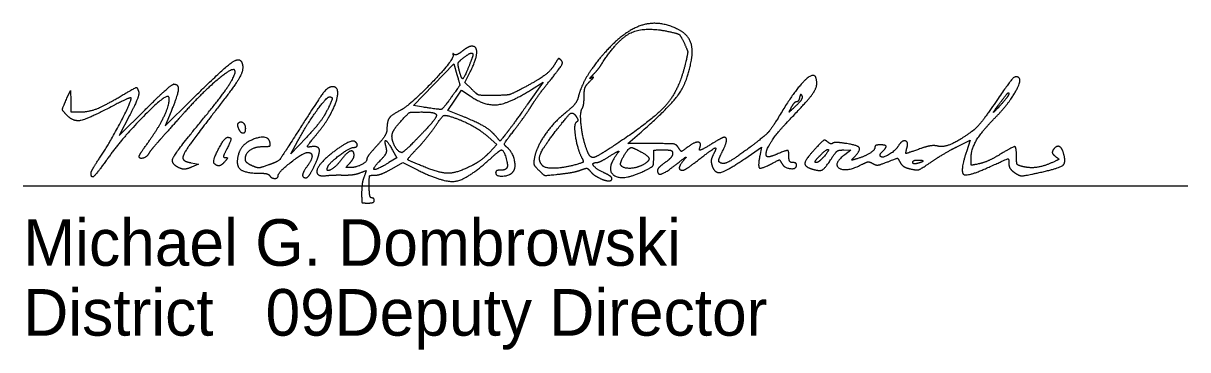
# Model space of a CAD drawing. Extents: x 0 to 45.4, y -2.2 to 22.
# Drawn here: x 26.722 to 30.222, y 3.58 to 4.561 of the extents above; entities that cross this region are included whole.
import ezdxf

# ---------------------------------------------------------------- set-up
doc = ezdxf.new("R2010")
doc.units = 0
doc.layers.add('SH_Data', color=7, linetype='Continuous')
doc.layers.add('SH_Text', color=7, linetype='Continuous')

msp = doc.modelspace()

# ---------------------------------------------------------------- linework, layer by layer
at = {"layer": 'SH_Data'}
msp.add_line((26.722, 4.0723), (30.222, 4.0723), dxfattribs=at)
at = {"layer": 'SH_Text'}
for p, q in [((29.063, 4.3434), (29.063, 4.3434)), ((27.3692, 4.2454), (27.3692, 4.2454)), ((27.296, 4.1396), (27.296, 4.1396)), ((26.9258, 4.1113), (26.9258, 4.1113))]:
    msp.add_line(p, q, dxfattribs=at)
for points in [[(27.9252, 4.3088), (27.8948, 4.3136), (28.0157, 4.4393), (28.0252, 4.4072)], [(28.0691, 4.3637), (28.0492, 4.3835), (28.0651, 4.4147)], [(28.2496, 4.3621), (28.2847, 4.3843), (28.238, 4.3183)], [(26.8533, 4.3362), (26.8638, 4.359), (26.8644, 4.3267)], [(28.0386, 4.283), (27.9983, 4.2993), (28.0187, 4.3297), (28.0392, 4.3601), (28.065, 4.3425)], [(27.1662, 4.2962), (27.1483, 4.2526), (27.2252, 4.3286)], [(27.0417, 4.2842), (27.0104, 4.2235), (27.0879, 4.3008)], [(27.5718, 4.2166), (27.5264, 4.169), (27.5472, 4.2077)], [(28.119, 4.22), (28.1456, 4.197), (28.1228, 4.1728)], [(28.6114, 4.1994), (28.5392, 4.1994), (28.574, 4.2298)], [(29.5295, 4.1906), (29.5682, 4.2099), (29.5568, 4.1751)], [(27.8319, 4.1801), (27.845, 4.1571), (27.8205, 4.1422)], [(28.8903, 4.154), (28.9406, 4.1884), (28.9357, 4.1625)], [(29.1888, 4.1803), (29.2096, 4.1801), (29.1913, 4.166)], [(27.2266, 4.1417), (27.2488, 4.1373), (27.228, 4.1287)], [(27.8293, 4.1236), (27.8625, 4.1426), (27.9084, 4.1197)]]:
    msp.add_lwpolyline(points, dxfattribs=at)
for points in [[(28.689, 4.5431), (28.6322, 4.5715), (28.5268, 4.5374), (28.4692, 4.4719)], [(28.461, 4.4394), (28.5081, 4.5131), (28.5886, 4.5518), (28.662, 4.5362)], [(28.662, 4.5362), (28.6896, 4.5303), (28.6975, 4.5245), (28.708, 4.5024)], [(28.7307, 4.454), (28.7361, 4.4868), (28.7161, 4.5296), (28.689, 4.5431)], [(28.0706, 4.492), (28.0649, 4.492), (28.0517, 4.4853), (28.0412, 4.4771)], [(28.0651, 4.4147), (28.0834, 4.4505), (28.0863, 4.492), (28.0706, 4.492)], [(28.708, 4.5024), (28.7188, 4.4797), (28.7193, 4.4702), (28.7117, 4.4383)], [(27.2252, 4.3286), (27.3196, 4.4219), (27.3721, 4.4608), (27.379, 4.4427)], [(28.0139, 4.4648), (28.0175, 4.453), (27.8844, 4.3142), (27.8551, 4.2992)], [(28.0168, 4.4676), (28.0138, 4.4706), (28.0125, 4.4693), (28.0139, 4.4648)], [(28.0412, 4.4771), (28.0308, 4.4689), (28.0198, 4.4646), (28.0168, 4.4676)], [(28.0318, 4.4216), (28.0278, 4.4377), (28.0304, 4.4453), (28.0433, 4.4558)], [(28.0433, 4.4558), (28.0592, 4.4687), (28.0734, 4.4733), (28.0734, 4.4656)], [(28.0734, 4.4656), (28.0734, 4.4636), (28.0679, 4.4482), (28.0612, 4.4314)], [(28.3081, 4.3928), (28.336, 4.4276), (28.3449, 4.4439), (28.339, 4.4497)], [(28.339, 4.4497), (28.3332, 4.4555), (28.3287, 4.4539), (28.3233, 4.4444)], [(28.4692, 4.4719), (28.4355, 4.4337), (28.3976, 4.3699), (28.39, 4.3388)], [(28.574, 4.2298), (28.6662, 4.3105), (28.7196, 4.3869), (28.7307, 4.454)], [(27.357, 4.4206), (27.3493, 4.4283), (27.2583, 4.3513), (27.2058, 4.2925)], [(27.2639, 4.2754), (27.3181, 4.3408), (27.3644, 4.4131), (27.357, 4.4206)], [(27.379, 4.4427), (27.3859, 4.4247), (27.3639, 4.3814), (27.3171, 4.321)], [(28.0612, 4.4314), (28.0468, 4.3956), (28.039, 4.393), (28.0318, 4.4216)], [(28.3233, 4.4444), (28.3102, 4.4212), (28.2769, 4.3945), (28.2295, 4.369)], [(28.4344, 4.4063), (28.4428, 4.4147), (28.4547, 4.4296), (28.461, 4.4394)], [(28.7117, 4.4383), (28.6928, 4.3596), (28.6163, 4.2716), (28.4999, 4.1947)], [(27.0879, 4.3008), (27.1306, 4.3433), (27.1697, 4.378), (27.1748, 4.378)], [(27.1748, 4.378), (27.1895, 4.378), (27.1859, 4.3438), (27.1662, 4.2962)], [(28.0252, 4.4072), (28.0343, 4.3762), (28.0338, 4.3738), (28.0099, 4.3404)], [(28.2498, 4.3135), (28.2603, 4.3303), (28.2865, 4.366), (28.3081, 4.3928)], [(28.4077, 4.3416), (28.4078, 4.3608), (28.4133, 4.3752), (28.4249, 4.3864)], [(28.4249, 4.3864), (28.4343, 4.3956), (28.4369, 4.4003), (28.4306, 4.397)], [(28.4306, 4.397), (28.4243, 4.3937), (28.426, 4.3979), (28.4344, 4.4063)], [(29.107, 4.3794), (29.107, 4.4207), (29.0453, 4.3676), (28.9943, 4.2825)], [(29.0148, 4.2602), (29.0742, 4.3222), (29.107, 4.3647), (29.107, 4.3794)], [(29.7133, 4.3981), (29.7036, 4.4041), (29.6836, 4.3813), (29.6311, 4.3046)], [(29.6423, 4.2763), (29.6811, 4.3155), (29.725, 4.3908), (29.7133, 4.3981)], [(26.8906, 4.2944), (26.9185, 4.2944), (26.9676, 4.314), (27.0259, 4.3484)], [(27.16, 4.338), (27.1567, 4.3547), (27.0231, 4.2213), (26.9736, 4.152)], [(27.0259, 4.3484), (27.0589, 4.3678), (27.0637, 4.3689), (27.068, 4.3576)], [(27.068, 4.3576), (27.071, 4.3499), (27.0606, 4.3209), (27.0417, 4.2842)], [(27.652, 4.3704), (27.638, 4.3704), (27.6121, 4.3368), (27.5444, 4.2308)], [(27.647, 4.2905), (27.6658, 4.3261), (27.6685, 4.3704), (27.652, 4.3704)], [(28.0099, 4.3404), (27.9839, 4.3042), (27.9749, 4.3008), (27.9252, 4.3088)], [(28.065, 4.3425), (28.1092, 4.3123), (28.1835, 4.3202), (28.2496, 4.3621)], [(28.1363, 4.3441), (28.0952, 4.3439), (28.0864, 4.3464), (28.0691, 4.3637)], [(28.2295, 4.369), (28.1921, 4.3489), (28.1748, 4.3443), (28.1363, 4.3441)], [(28.4013, 4.3036), (28.4048, 4.309), (28.4076, 4.3261), (28.4077, 4.3416)], [(29.0445, 4.3131), (29.0575, 4.3253), (29.0658, 4.3389), (29.063, 4.3434)], [(29.063, 4.3434), (29.06, 4.3481), (29.0569, 4.346), (29.0553, 4.3381)], [(29.6846, 4.3503), (29.6846, 4.3464), (29.674, 4.3314), (29.661, 4.3169)], [(29.668, 4.3353), (29.6771, 4.3474), (29.6846, 4.3541), (29.6846, 4.3503)], [(26.8549, 4.2828), (26.8398, 4.2979), (26.8395, 4.3061), (26.8533, 4.3362)], [(26.9858, 4.3097), (26.9165, 4.2734), (26.8732, 4.2645), (26.8549, 4.2828)], [(26.8644, 4.3267), (26.865, 4.2952), (26.8656, 4.2944), (26.8906, 4.2944)], [(26.9532, 4.1588), (26.983, 4.2029), (27.0501, 4.3323), (27.0455, 4.3368)], [(27.0455, 4.3368), (27.044, 4.3383), (27.0171, 4.3262), (26.9858, 4.3097)], [(27.0967, 4.2021), (27.1296, 4.2478), (27.1634, 4.3204), (27.16, 4.338)], [(27.3171, 4.321), (27.2394, 4.2207), (27.1991, 4.1624), (27.2018, 4.1543)], [(27.5472, 4.2077), (27.5716, 4.2531), (27.6339, 4.3398), (27.6421, 4.3399)], [(27.6421, 4.3399), (27.6516, 4.3401), (27.6486, 4.3258), (27.6325, 4.2942)], [(28.238, 4.3183), (28.2122, 4.282), (28.1839, 4.2429), (28.1749, 4.2315)], [(28.1978, 4.2401), (28.2159, 4.2637), (28.2393, 4.2967), (28.2498, 4.3135)], [(28.39, 4.3388), (28.3873, 4.3276), (28.3712, 4.3076), (28.3543, 4.2942)], [(29.03, 4.3078), (29.0225, 4.2937), (29.0249, 4.2946), (29.0445, 4.3131)], [(29.0459, 4.3248), (29.0422, 4.3248), (29.035, 4.3172), (29.03, 4.3078)], [(29.0553, 4.3381), (29.0539, 4.3308), (29.0496, 4.3248), (29.0459, 4.3248)], [(29.661, 4.3169), (29.6364, 4.2896), (29.6394, 4.2975), (29.668, 4.3353)], [(27.2058, 4.2925), (27.1751, 4.2582), (27.1397, 4.2186), (27.1272, 4.2046)], [(27.1962, 4.1242), (27.1636, 4.1368), (27.1806, 4.1749), (27.2639, 4.2754)], [(27.6325, 4.2942), (27.6241, 4.2777), (27.5967, 4.2428), (27.5718, 4.2166)], [(27.6005, 4.2236), (27.6173, 4.2437), (27.6382, 4.2739), (27.647, 4.2905)], [(27.8551, 4.2992), (27.8284, 4.2855), (27.815, 4.2662), (27.815, 4.2416)], [(27.8564, 4.2659), (27.88, 4.2916), (27.8864, 4.2944), (27.9206, 4.2944)], [(27.9633, 4.2867), (27.9659, 4.2824), (27.9451, 4.255), (27.9169, 4.2259)], [(27.9206, 4.2944), (27.9414, 4.2944), (27.9607, 4.2909), (27.9633, 4.2867)], [(27.9596, 4.2508), (27.9798, 4.2797), (27.9881, 4.2861), (28.0006, 4.2824)], [(28.0006, 4.2824), (28.0364, 4.2719), (28.0941, 4.2415), (28.119, 4.22)], [(28.1419, 4.2221), (28.1282, 4.2386), (28.0847, 4.2642), (28.0386, 4.283)], [(28.3543, 4.2942), (28.3181, 4.2655), (28.265, 4.1902), (28.2587, 4.1586)], [(28.3147, 4.2269), (28.3574, 4.2828), (28.3746, 4.2958), (28.3848, 4.2794)], [(28.3848, 4.2794), (28.3892, 4.2724), (28.3889, 4.2664), (28.3838, 4.2633)], [(28.4167, 4.1785), (28.4044, 4.21), (28.3943, 4.2925), (28.4013, 4.3036)], [(28.9943, 4.2825), (28.9718, 4.2449), (28.9501, 4.2214), (28.9097, 4.191)], [(29.5706, 4.1545), (29.5706, 4.1814), (29.6031, 4.2367), (29.6423, 4.2763)], [(29.6311, 4.3046), (29.6106, 4.2747), (29.5843, 4.2435), (29.5727, 4.2353)], [(27.3692, 4.2454), (27.3667, 4.2518), (27.3666, 4.259), (27.3689, 4.2613)], [(27.3689, 4.2613), (27.3756, 4.268), (27.3894, 4.2567), (27.3894, 4.2446)], [(27.3894, 4.2446), (27.3894, 4.23), (27.3749, 4.2306), (27.3692, 4.2454)], [(27.815, 4.2416), (27.815, 4.2328), (27.8013, 4.2108), (27.7846, 4.1927)], [(27.8302, 4.222), (27.8303, 4.2305), (27.842, 4.2502), (27.8564, 4.2659)], [(27.9073, 4.1861), (27.9221, 4.2018), (27.9456, 4.2309), (27.9596, 4.2508)], [(28.176, 4.188), (28.1666, 4.1959), (28.1698, 4.2035), (28.1978, 4.2401)], [(28.3838, 4.2633), (28.3755, 4.2581), (28.3878, 4.1813), (28.4011, 4.1561)], [(28.9575, 4.1602), (28.9491, 4.1686), (28.9817, 4.2256), (29.0148, 4.2602)], [(29.5727, 4.2353), (29.5319, 4.2065), (29.4872, 4.1877), (29.4699, 4.192)], [(27.0702, 4.1614), (27.0702, 4.1635), (27.0821, 4.1818), (27.0967, 4.2021)], [(27.1272, 4.2046), (27.1147, 4.1906), (27.1017, 4.1742), (27.0983, 4.1683)], [(27.296, 4.1396), (27.2897, 4.1459), (27.3268, 4.2184), (27.3363, 4.2184)], [(27.3363, 4.2184), (27.3469, 4.2184), (27.3456, 4.2059), (27.3322, 4.18)], [(27.4635, 4.2026), (27.4584, 4.2275), (27.3793, 4.201), (27.3699, 4.1712)], [(27.443, 4.1906), (27.46, 4.1906), (27.4654, 4.1937), (27.4635, 4.2026)], [(27.5444, 4.2308), (27.4968, 4.1562), (27.4868, 4.1449), (27.4595, 4.1353)], [(27.5832, 4.1894), (27.574, 4.1877), (27.5793, 4.1981), (27.6005, 4.2236)], [(27.7173, 4.2063), (27.7099, 4.2109), (27.6528, 4.1757), (27.6265, 4.1503)], [(27.715, 4.188), (27.7252, 4.188), (27.7268, 4.2005), (27.7173, 4.2063)], [(27.8129, 4.1876), (27.8069, 4.2105), (27.8168, 4.2066), (27.8319, 4.1801)], [(27.8598, 4.1728), (27.8499, 4.1728), (27.8302, 4.2056), (27.8302, 4.222)], [(27.9169, 4.2259), (27.8887, 4.1967), (27.863, 4.1728), (27.8598, 4.1728)], [(28.1749, 4.2315), (28.156, 4.2075), (28.1544, 4.207), (28.1419, 4.2221)], [(28.2837, 4.1323), (28.2692, 4.1468), (28.281, 4.1827), (28.3147, 4.2269)], [(28.7545, 4.1837), (28.7615, 4.202), (28.7414, 4.2055), (28.72, 4.1897)], [(28.8285, 4.2184), (28.8259, 4.2184), (28.8072, 4.2083), (28.7871, 4.1959)], [(28.8214, 4.1717), (28.8337, 4.1955), (28.8372, 4.2184), (28.8285, 4.2184)], [(29.1397, 4.2045), (29.1314, 4.2113), (29.1237, 4.2071), (29.1029, 4.1844)], [(29.1548, 4.2004), (29.1523, 4.1978), (29.1455, 4.1997), (29.1397, 4.2045)], [(29.194, 4.1999), (29.175, 4.2027), (29.1574, 4.203), (29.1548, 4.2004)], [(29.3784, 4.188), (29.383, 4.2057), (29.3624, 4.2096), (29.3525, 4.193)], [(27.0983, 4.1683), (27.0927, 4.1584), (27.0702, 4.1529), (27.0702, 4.1614)], [(27.3322, 4.18), (27.3243, 4.1648), (27.3234, 4.1576), (27.3293, 4.1576)], [(27.3699, 4.1712), (27.359, 4.137), (27.3863, 4.1105), (27.4321, 4.1105)], [(27.3894, 4.1525), (27.3894, 4.1698), (27.4186, 4.1906), (27.443, 4.1906)], [(27.4882, 4.1038), (27.4882, 4.1136), (27.564, 4.1728), (27.5766, 4.1728)], [(27.5766, 4.1728), (27.5902, 4.1728), (27.5895, 4.1502), (27.5754, 4.1315)], [(27.5964, 4.1313), (27.6146, 4.1689), (27.6089, 4.1941), (27.5832, 4.1894)], [(27.6373, 4.13), (27.6421, 4.1417), (27.7041, 4.188), (27.715, 4.188)], [(27.7162, 4.1639), (27.7162, 4.1805), (27.6939, 4.1729), (27.6775, 4.1507)], [(27.7846, 4.1927), (27.7679, 4.1746), (27.7542, 4.1564), (27.7542, 4.1523)], [(27.7956, 4.1496), (27.8101, 4.1647), (27.8157, 4.177), (27.8129, 4.1876)], [(27.9334, 4.1269), (27.8782, 4.1491), (27.8763, 4.1534), (27.9073, 4.1861)], [(28.1228, 4.1728), (28.1103, 4.1595), (28.0869, 4.1419), (28.071, 4.1337)], [(28.1248, 4.1531), (28.1414, 4.1681), (28.1569, 4.1804), (28.1591, 4.1804)], [(28.1591, 4.1804), (28.1657, 4.1804), (28.1799, 4.1336), (28.1755, 4.1264)], [(28.1938, 4.1144), (28.204, 4.1267), (28.1925, 4.1743), (28.176, 4.188)], [(28.4343, 4.1576), (28.4291, 4.1576), (28.4212, 4.167), (28.4167, 4.1785)], [(28.4999, 4.1947), (28.4691, 4.1743), (28.4396, 4.1576), (28.4343, 4.1576)], [(28.4858, 4.1627), (28.5035, 4.1738), (28.5142, 4.1781), (28.5097, 4.1722)], [(28.5097, 4.1722), (28.4709, 4.1221), (28.5247, 4.086), (28.5902, 4.1182)], [(28.5181, 4.1347), (28.5142, 4.141), (28.5424, 4.188), (28.5502, 4.188)], [(28.5502, 4.188), (28.5517, 4.188), (28.563, 4.1828), (28.5754, 4.1764)], [(28.5754, 4.1764), (28.6012, 4.1631), (28.6043, 4.1464), (28.5831, 4.1351)], [(28.6914, 4.1869), (28.685, 4.1971), (28.6701, 4.1994), (28.6114, 4.1994)], [(28.6168, 4.154), (28.6168, 4.1791), (28.6185, 4.1804), (28.651, 4.1804)], [(28.651, 4.1804), (28.6657, 4.1804), (28.6738, 4.1766), (28.6738, 4.1695)], [(28.6738, 4.1695), (28.6738, 4.1636), (28.6635, 4.1514), (28.651, 4.1424)], [(28.72, 4.1897), (28.7011, 4.1757), (28.6987, 4.1755), (28.6914, 4.1869)], [(28.7507, 4.15), (28.7933, 4.1837), (28.8079, 4.1886), (28.7952, 4.1649)], [(28.7871, 4.1959), (28.767, 4.1835), (28.7523, 4.178), (28.7545, 4.1837)], [(28.8135, 4.1446), (28.8113, 4.1468), (28.8149, 4.159), (28.8214, 4.1717)], [(28.9097, 4.191), (28.8587, 4.1527), (28.8228, 4.1353), (28.8135, 4.1446)], [(28.9878, 4.1679), (28.973, 4.1618), (28.9594, 4.1583), (28.9575, 4.1602)], [(29.0234, 4.1564), (29.0234, 4.1779), (29.0168, 4.18), (28.9878, 4.1679)], [(29.1029, 4.1844), (29.0732, 4.1521), (29.0693, 4.1306), (29.0918, 4.1234)], [(29.1146, 4.1614), (29.1355, 4.1837), (29.1464, 4.1801), (29.126, 4.1577)], [(29.1508, 4.1539), (29.1636, 4.1737), (29.1732, 4.1804), (29.1888, 4.1803)], [(29.1913, 4.166), (29.1536, 4.137), (29.1973, 4.1132), (29.2438, 4.1373)], [(29.2191, 4.1583), (29.2393, 4.1795), (29.2302, 4.1944), (29.194, 4.1999)], [(29.2818, 4.1889), (29.2818, 4.1803), (29.2531, 4.1615), (29.2286, 4.1541)], [(29.297, 4.1956), (29.2886, 4.1956), (29.2818, 4.1926), (29.2818, 4.1889)], [(29.3032, 4.1745), (29.3165, 4.1877), (29.3142, 4.1956), (29.297, 4.1956)], [(29.2992, 4.1605), (29.2964, 4.1632), (29.2983, 4.1695), (29.3032, 4.1745)], [(29.3525, 4.193), (29.3437, 4.1783), (29.305, 4.1547), (29.2992, 4.1605)], [(29.4195, 4.1846), (29.3768, 4.1695), (29.3736, 4.1697), (29.3784, 4.188)], [(29.4699, 4.192), (29.4605, 4.1944), (29.4378, 4.191), (29.4195, 4.1846)], [(29.4516, 4.1447), (29.4732, 4.1593), (29.5082, 4.18), (29.5295, 4.1906)], [(29.5568, 4.1751), (29.5367, 4.1143), (29.5607, 4.0994), (29.6285, 4.1305)], [(29.6565, 4.1662), (29.6364, 4.154), (29.6089, 4.1417), (29.5953, 4.1388)], [(29.7074, 4.1573), (29.7074, 4.1894), (29.6976, 4.1912), (29.6565, 4.1662)], [(29.7758, 4.1123), (29.8372, 4.1259), (29.8574, 4.1432), (29.8477, 4.1739)], [(29.8169, 4.1793), (29.8139, 4.1745), (29.8171, 4.1664), (29.8239, 4.1614)], [(29.8477, 4.1739), (29.8426, 4.1897), (29.8252, 4.1927), (29.8169, 4.1793)], [(26.9258, 4.1113), (26.9258, 4.115), (26.9381, 4.1364), (26.9532, 4.1588)], [(26.9736, 4.152), (26.9424, 4.1082), (26.9258, 4.0941), (26.9258, 4.1113)], [(27.2018, 4.1543), (27.2032, 4.1499), (27.2144, 4.1442), (27.2266, 4.1417)], [(27.3286, 4.1462), (27.3188, 4.1344), (27.3042, 4.1314), (27.296, 4.1396)], [(27.3293, 4.1576), (27.3356, 4.1576), (27.3354, 4.1544), (27.3286, 4.1462)], [(27.409, 4.1332), (27.3982, 4.1381), (27.3894, 4.1468), (27.3894, 4.1525)], [(27.4595, 4.1353), (27.435, 4.1266), (27.4244, 4.1261), (27.409, 4.1332)], [(27.5754, 4.1315), (27.5625, 4.1144), (27.5607, 4.0968), (27.5719, 4.0968)], [(27.5719, 4.0968), (27.5761, 4.0968), (27.5871, 4.1124), (27.5964, 4.1313)], [(27.6265, 4.1503), (27.6028, 4.1275), (27.6064, 4.0997), (27.6326, 4.1031)], [(27.6775, 4.1507), (27.6613, 4.1288), (27.6302, 4.1128), (27.6373, 4.13)], [(27.7033, 4.1272), (27.6922, 4.1272), (27.6922, 4.1285), (27.7036, 4.1411)], [(27.7542, 4.1523), (27.7542, 4.1436), (27.7209, 4.1272), (27.7033, 4.1272)], [(27.7036, 4.1411), (27.7105, 4.1488), (27.7162, 4.159), (27.7162, 4.1639)], [(27.8205, 4.1422), (27.7833, 4.1195), (27.7704, 4.1233), (27.7956, 4.1496)], [(27.9084, 4.1197), (27.986, 4.081), (28.0571, 4.0919), (28.1248, 4.1531)], [(28.071, 4.1337), (28.0277, 4.1115), (27.9779, 4.109), (27.9334, 4.1269)], [(28.2587, 4.1586), (28.2553, 4.1419), (28.2584, 4.1322), (28.2711, 4.1195)], [(28.3794, 4.1352), (28.3472, 4.1263), (28.2914, 4.1246), (28.2837, 4.1323)], [(28.4011, 4.1561), (28.4067, 4.1455), (28.4029, 4.1418), (28.3794, 4.1352)], [(28.4669, 4.112), (28.4429, 4.1234), (28.4293, 4.1424), (28.4453, 4.1424)], [(28.4453, 4.1424), (28.4499, 4.1424), (28.4682, 4.1515), (28.4858, 4.1627)], [(28.5831, 4.1351), (28.5645, 4.1251), (28.5241, 4.1249), (28.5181, 4.1347)], [(28.5902, 4.1182), (28.6117, 4.1288), (28.6168, 4.1357), (28.6168, 4.154)], [(28.651, 4.1424), (28.6385, 4.1335), (28.6282, 4.123), (28.6282, 4.1191)], [(28.6282, 4.1191), (28.6282, 4.104), (28.6548, 4.1133), (28.6882, 4.1401)], [(28.6882, 4.1401), (28.7075, 4.1556), (28.7172, 4.1613), (28.7099, 4.1528)], [(28.7099, 4.1528), (28.6951, 4.1357), (28.6924, 4.1196), (28.7044, 4.1196)], [(28.7044, 4.1196), (28.7087, 4.1196), (28.7295, 4.1333), (28.7507, 4.15)], [(28.7952, 4.1649), (28.7907, 4.1564), (28.7891, 4.1427), (28.7917, 4.1345)], [(28.7917, 4.1345), (28.7997, 4.1092), (28.8349, 4.1161), (28.8903, 4.154)], [(28.9357, 4.1625), (28.9295, 4.1297), (28.9399, 4.1229), (28.9711, 4.1391)], [(28.9711, 4.1391), (28.9933, 4.1506), (28.9959, 4.1506), (29.0021, 4.1394)], [(29.0021, 4.1394), (29.0095, 4.1262), (29.0462, 4.1224), (29.0462, 4.1348)], [(29.0348, 4.1424), (29.0285, 4.1424), (29.0234, 4.1487), (29.0234, 4.1564)], [(29.0462, 4.1348), (29.0462, 4.139), (29.0411, 4.1424), (29.0348, 4.1424)], [(29.0918, 4.1234), (29.1151, 4.116), (29.1319, 4.1247), (29.1508, 4.1539)], [(29.1045, 4.1424), (29.1002, 4.1424), (29.1048, 4.151), (29.1146, 4.1614)], [(29.126, 4.1577), (29.1184, 4.1493), (29.1088, 4.1424), (29.1045, 4.1424)], [(29.2286, 4.1541), (29.2131, 4.1494), (29.2113, 4.1501), (29.2191, 4.1583)], [(29.2438, 4.1373), (29.257, 4.1442), (29.2666, 4.1449), (29.2754, 4.1396)], [(29.2754, 4.1396), (29.2844, 4.1342), (29.2972, 4.1356), (29.3192, 4.1442)], [(29.3192, 4.1442), (29.3486, 4.1558), (29.3507, 4.1557), (29.3578, 4.1425)], [(29.3578, 4.1425), (29.3619, 4.1348), (29.3759, 4.1261), (29.3889, 4.1233)], [(29.3889, 4.1233), (29.4082, 4.119), (29.4195, 4.1229), (29.4516, 4.1447)], [(29.3958, 4.1431), (29.3958, 4.1469), (29.4026, 4.15), (29.411, 4.15)], [(29.411, 4.1402), (29.4026, 4.138), (29.3958, 4.1393), (29.3958, 4.1431)], [(29.411, 4.15), (29.4194, 4.15), (29.4262, 4.1487), (29.4262, 4.1471)], [(29.4262, 4.1471), (29.4262, 4.1455), (29.4194, 4.1424), (29.411, 4.1402)], [(29.5953, 4.1388), (29.5722, 4.1339), (29.5706, 4.1349), (29.5706, 4.1545)], [(29.6285, 4.1305), (29.6787, 4.1534), (29.6846, 4.1542), (29.6846, 4.1376)], [(29.6846, 4.1376), (29.6846, 4.1307), (29.6906, 4.1206), (29.6979, 4.115)], [(29.7264, 4.1303), (29.7115, 4.1341), (29.7074, 4.14), (29.7074, 4.1573)], [(29.8181, 4.1441), (29.7904, 4.1314), (29.7477, 4.125), (29.7264, 4.1303)], [(29.8239, 4.1614), (29.835, 4.1533), (29.8344, 4.1515), (29.8181, 4.1441)], [(27.228, 4.1287), (27.2165, 4.1239), (27.2022, 4.1219), (27.1962, 4.1242)], [(27.4321, 4.1105), (27.4463, 4.1105), (27.4597, 4.1074), (27.4621, 4.1037)], [(27.4621, 4.1037), (27.4676, 4.0947), (27.4882, 4.0948), (27.4882, 4.1038)], [(27.6326, 4.1031), (27.643, 4.1045), (27.6659, 4.1053), (27.6833, 4.105)], [(27.6833, 4.105), (27.7008, 4.1046), (27.7237, 4.1077), (27.7343, 4.1117)], [(27.7343, 4.1117), (27.7527, 4.1187), (27.7532, 4.1181), (27.7463, 4.0998)], [(27.7463, 4.0998), (27.7423, 4.0893), (27.739, 4.0672), (27.739, 4.0507)], [(27.7618, 4.0702), (27.7618, 4.1006), (27.7637, 4.1044), (27.7789, 4.1045)], [(27.7789, 4.1045), (27.7883, 4.1046), (27.811, 4.1132), (27.8293, 4.1236)], [(28.1565, 4.1196), (28.1484, 4.1196), (28.1418, 4.1162), (28.1418, 4.112)], [(28.1418, 4.112), (28.1418, 4.1008), (28.1842, 4.1028), (28.1938, 4.1144)], [(28.1755, 4.1264), (28.1732, 4.1227), (28.1647, 4.1196), (28.1565, 4.1196)], [(28.2711, 4.1195), (28.2862, 4.1045), (28.2928, 4.1032), (28.3334, 4.1078)], [(28.3334, 4.1078), (28.3584, 4.1106), (28.3875, 4.1162), (28.398, 4.1203)], [(28.398, 4.1203), (28.4123, 4.1257), (28.4195, 4.1248), (28.4258, 4.1169)], [(28.4258, 4.1169), (28.4305, 4.1111), (28.4412, 4.1026), (28.4496, 4.098)], [(28.4496, 4.098), (28.4672, 4.0884), (28.4915, 4.0866), (28.4912, 4.0949)], [(28.4912, 4.0949), (28.4911, 4.0981), (28.4802, 4.1058), (28.4669, 4.112)], [(29.6979, 4.115), (29.7138, 4.1029), (29.7304, 4.1023), (29.7758, 4.1123)], [(27.7694, 4.036), (27.7652, 4.036), (27.7618, 4.0514), (27.7618, 4.0702)], [(27.739, 4.0507), (27.739, 4.0239), (27.7409, 4.0208), (27.758, 4.0208)], [(27.758, 4.0208), (27.7684, 4.0208), (27.777, 4.0242), (27.777, 4.0284)], [(27.777, 4.0284), (27.777, 4.0326), (27.7736, 4.036), (27.7694, 4.036)]]:
    msp.add_open_spline(points, degree=2, dxfattribs=at)

# ---------------------------------------------------------------- texts
for s, p in [('Michael G. Dombrowski', (26.722, 3.8323)), ('District       Deputy Director', (26.722, 3.6223)), ('              09', (26.722, 3.6223))]:
    msp.add_text(s, height=0.14, dxfattribs=at).set_placement(p)

doc.saveas('drawing.dxf')
